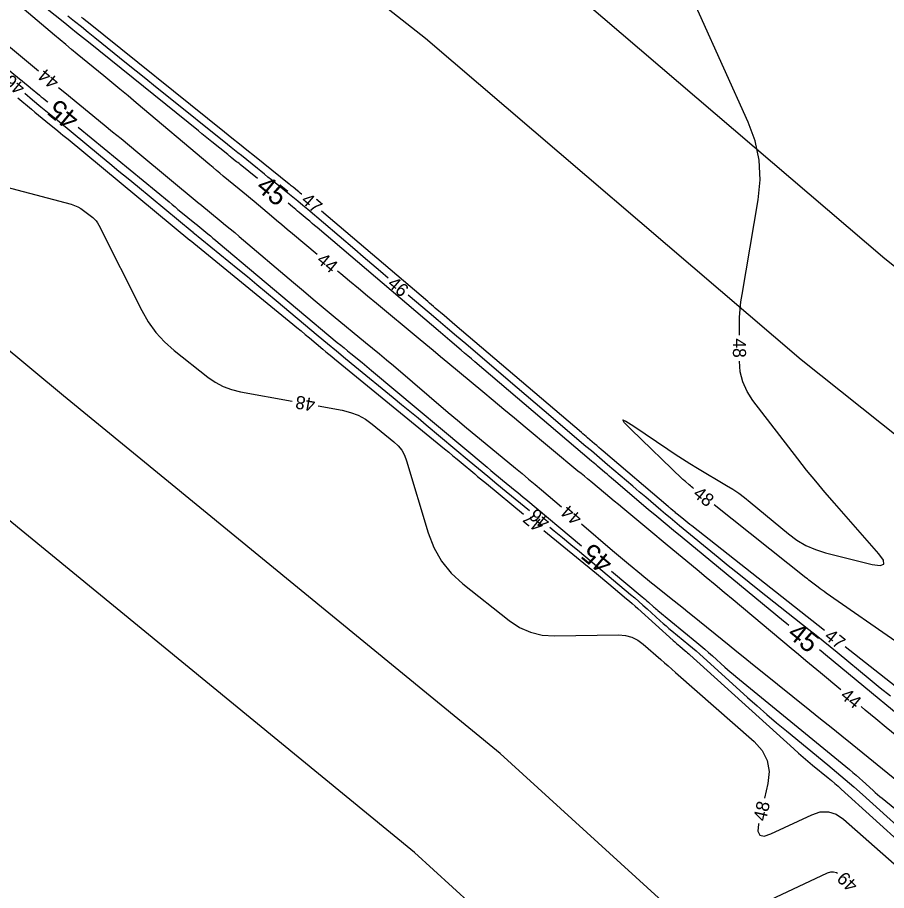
# Model space of a CAD drawing. Extents: x 2384780 to 2405861, y 547869 to 573706.
# Drawn here: x 2392904.4 to 2393037.1, y 552728.4 to 552861.7 of the extents above; entities that cross this region are included whole.
import ezdxf

# ---------------------------------------------------------------- set-up
doc = ezdxf.new("R2010")
doc.units = 0
for name, color, linetype in [('Old_Level_60', 7, 'Continuous'), ('Old_Level_61', 7, 'Continuous'), ('Prop Buffer Zone 1', 7, 'Continuous'), ('Prop Buffer Zone 2', 7, 'Continuous')]:
    doc.layers.add(name, color=color, linetype=linetype)

msp = doc.modelspace()

# ---------------------------------------------------------------- linework, layer by layer
at = {"layer": 'Old_Level_60'}
for points in [[(2393014.651, 552813.187), (2393014.651, 552814.72), (2393014.67575, 552815.89675), (2393014.75, 552817.06925), (2393014.874, 552818.23775), (2393015.0475, 552819.402), (2393017.507, 552833.8205), (2393017.8075, 552836.88125), (2393017.6545, 552839.88425), (2393017.048, 552842.82925), (2393015.9885, 552845.7165), (2393001.1235, 552878.74575)], [(2392950.20325, 552825.51225), (2392946.424, 552828.65525), (2392945.61225, 552829.33125), (2392944.8015, 552830.00825), (2392943.99175, 552830.68675), (2392943.183, 552831.36625), (2392940.5425, 552833.58775), (2392939.976, 552834.063), (2392939.40825, 552834.5365), (2392938.83875, 552835.0085), (2392938.26825, 552835.4785), (2392935.84425, 552837.46975), (2392935.32575, 552837.89725), (2392934.80825, 552838.32625), (2392934.29225, 552838.757), (2392933.7775, 552839.18925), (2392922.5335, 552848.666), (2392921.30425, 552849.69875), (2392920.0715, 552850.72775), (2392918.83575, 552851.753), (2392917.59675, 552852.77425), (2392913.54375, 552856.10375), (2392912.6765, 552856.819), (2392911.81225, 552857.53725), (2392910.9505, 552858.259), (2392910.0915, 552858.98375), (2392894.82625, 552871.91475)], [(2392961.027, 552821.88525), (2392959.836, 552822.899), (2392958.52525, 552824.015), (2392957.21475, 552825.13125), (2392955.90425, 552826.24775), (2392948.76075, 552832.33575), (2392948.0065, 552832.97425), (2392947.248, 552833.60775), (2392946.485, 552834.23625), (2392945.71825, 552834.8595), (2392943.20575, 552836.8875), (2392942.66725, 552837.32175), (2392942.1285, 552837.756), (2392941.58975, 552838.18975), (2392941.0505, 552838.62325), (2392938.60325, 552840.58975), (2392938.07875, 552841.011), (2392937.55425, 552841.4325), (2392937.03, 552841.85375), (2392936.5055, 552842.27525), (2392926.993, 552849.9185), (2392925.51425, 552851.10725), (2392924.036, 552852.297), (2392922.55825, 552853.48725), (2392921.08125, 552854.67825), (2392916.257, 552858.57025), (2392915.223, 552859.404), (2392914.1885, 552860.23725), (2392913.1535, 552861.06975), (2392912.11825, 552861.90175)], [(2392947.81175, 552834.6855), (2392947.785, 552834.7085), (2392947.58, 552834.8795), (2392947.374, 552835.04925), (2392947.167, 552835.2175), (2392946.4885, 552835.76525), (2392946.343, 552835.8825), (2392946.1975, 552835.99975), (2392946.052, 552836.117), (2392945.90625, 552836.234), (2392940.5875, 552840.50775), (2392939.44775, 552841.4235), (2392938.308, 552842.33925), (2392937.16825, 552843.25525), (2392936.0285, 552844.171), (2392915.011, 552861.05875), (2392915.0015, 552861.06625), (2392914.992, 552861.074), (2392914.98225, 552861.08175), (2392914.97275, 552861.0895), (2392914.9415, 552861.11475), (2392914.93475, 552861.12), (2392914.92825, 552861.1255), (2392914.9215, 552861.13075), (2392914.91475, 552861.13625), (2392914.51625, 552861.45625), (2392914.43175, 552861.52575), (2392914.349, 552861.59725), (2392914.26775, 552861.6705), (2392914.18825, 552861.7455)], [(2392900.331, 552859.599), (2392906.41775, 552854.54675), (2392907.621, 552853.54975)], [(2392905.52325, 552850.113), (2392906.743, 552849.10525), (2392908.00425, 552848.0635), (2392909.266, 552847.0225), (2392910.52825, 552845.98175), (2392917.10375, 552840.56225), (2392918.5125, 552839.4005), (2392919.921, 552838.2385), (2392921.329, 552837.076), (2392922.73675, 552835.91275), (2392931.11875, 552828.9845), (2392931.128, 552828.97675), (2392931.13725, 552828.96925), (2392931.14625, 552828.9615), (2392931.1555, 552828.954), (2392931.1855, 552828.92875), (2392931.19175, 552828.9235), (2392931.19825, 552828.918), (2392931.20475, 552828.91275), (2392931.21125, 552828.9075), (2392938.05975, 552823.3055), (2392939.5255, 552822.10275), (2392940.9875, 552820.89575), (2392942.446, 552819.68425), (2392943.90075, 552818.4685), (2392950.35075, 552813.061), (2392951.7345, 552811.90425), (2392953.122, 552810.75175), (2392954.51275, 552809.6035), (2392955.907, 552808.45925), (2392961.80175, 552803.63675), (2392963.06325, 552802.6015), (2392964.322, 552801.5625), (2392965.5775, 552800.52), (2392966.83, 552799.47375), (2392973.3925, 552793.97525), (2392974.8005, 552792.79925), (2392976.21175, 552791.62725), (2392977.6265, 552790.45925), (2392979.04475, 552789.2955), (2392982.592, 552786.393)], [(2392910.7075, 552851.0055), (2392911.64875, 552850.233), (2392917.66775, 552845.30125), (2392918.95675, 552844.2435), (2392920.24375, 552843.1835), (2392921.52925, 552842.1215), (2392922.813, 552841.05725), (2392932.17875, 552833.28025), (2392932.18825, 552833.27225), (2392932.1975, 552833.2645), (2392932.20675, 552833.25675), (2392932.216, 552833.24875), (2392932.2465, 552833.223), (2392932.253, 552833.2175), (2392932.2595, 552833.212), (2392932.266, 552833.20675), (2392932.2725, 552833.20125), (2392935.5135, 552830.54575), (2392936.20675, 552829.97525), (2392936.89725, 552829.4015), (2392937.58525, 552828.82475), (2392938.27075, 552828.24475), (2392946.5655, 552821.19325), (2392948.06875, 552819.9205), (2392949.57725, 552818.65425), (2392951.091, 552817.39425), (2392952.61, 552816.1405), (2392957.5805, 552812.05475), (2392958.64375, 552811.177), (2392959.703, 552810.2945), (2392960.75825, 552809.4075), (2392961.80975, 552808.51575), (2392970.18675, 552801.3795), (2392971.59025, 552800.18925), (2392972.999, 552799.0055), (2392974.41325, 552797.828), (2392975.8325, 552796.65675), (2392980.478, 552792.841), (2392981.47125, 552792.021), (2392982.46075, 552791.19625), (2392983.4465, 552790.36675), (2392984.428, 552789.5325), (2392987.47725, 552786.9285)], [(2392904.49125, 552849.3955), (2392906.543, 552847.6995), (2392907.09925, 552847.23975), (2392907.6555, 552846.7805), (2392908.21225, 552846.32125), (2392908.769, 552845.86225), (2392910.58775, 552844.363), (2392910.9775, 552844.0415), (2392911.367, 552843.72025), (2392911.7565, 552843.3985), (2392912.146, 552843.07675), (2392930.75675, 552827.69375), (2392930.76, 552827.69125), (2392930.763, 552827.68875), (2392930.76625, 552827.686), (2392930.7695, 552827.6835), (2392930.7795, 552827.67475), (2392930.78175, 552827.673), (2392930.784, 552827.67125), (2392930.78625, 552827.66925), (2392930.7885, 552827.6675), (2392946.4455, 552814.86025), (2392947.084, 552814.33625), (2392947.721, 552813.8105), (2392948.35625, 552813.28275), (2392948.99, 552812.753), (2392951.05775, 552811.0195), (2392951.5015, 552810.64875), (2392951.94625, 552810.27925), (2392952.392, 552809.911), (2392952.839, 552809.54425), (2392969.62475, 552795.81175), (2392970.263, 552795.288), (2392970.9, 552794.76225), (2392971.53525, 552794.23475), (2392972.169, 552793.70525), (2392974.2365, 552791.973), (2392974.68025, 552791.6025), (2392975.12475, 552791.23325), (2392975.5705, 552790.86525), (2392976.0175, 552790.4985), (2392981.702, 552785.84725)], [(2392884.42625, 552840.60725), (2392912.641, 552833.1545), (2392913.14875, 552832.99275), (2392913.63225, 552832.78225), (2392914.09125, 552832.523), (2392914.52625, 552832.215), (2392915.90675, 552831.129), (2392916.18675, 552830.88325), (2392916.43525, 552830.61175), (2392916.65175, 552830.31425), (2392916.83675, 552829.991), (2392923.4105, 552816.91125), (2392924.39525, 552815.1875), (2392925.548, 552813.60025), (2392926.8685, 552812.15), (2392928.357, 552810.83625), (2392933.49375, 552806.7685), (2392934.6295, 552805.97425), (2392935.8355, 552805.335), (2392937.1115, 552804.85075), (2392938.45775, 552804.5215), (2392946.3755, 552803.0785)], [(2393027.65, 552768.061), (2393007.35425, 552784.04225), (2393007.05725, 552784.2775), (2393006.7615, 552784.5145), (2393006.467, 552784.753), (2393006.174, 552784.993), (2393005.07525, 552785.89825), (2393004.94225, 552786.00825), (2393004.80975, 552786.1185), (2393004.67775, 552786.2295), (2393004.54625, 552786.341), (2393004.11725, 552786.70625), (2393004.02525, 552786.7845), (2393003.9335, 552786.86275), (2393003.8415, 552786.941), (2393003.7495, 552787.01925), (2392993.85825, 552795.44975), (2392993.52725, 552795.73175), (2392993.1965, 552796.0135), (2392992.8655, 552796.29525), (2392992.5345, 552796.577), (2392991.45325, 552797.49725), (2392991.2215, 552797.69425), (2392990.99, 552797.8915), (2392990.75825, 552798.089), (2392990.52675, 552798.28625), (2392971.21525, 552814.745), (2392970.80225, 552815.09675), (2392970.389, 552815.44875), (2392969.97575, 552815.8005), (2392969.5625, 552816.15225), (2392968.2125, 552817.30125), (2392967.923, 552817.5475), (2392967.63375, 552817.79375), (2392967.34475, 552818.04), (2392967.0555, 552818.28625), (2392950.85675, 552832.09175)], [(2393030.1475, 552758.9925), (2393027.01325, 552761.5885), (2393025.8915, 552762.519), (2393024.771, 552763.45125), (2393023.65175, 552764.38475), (2393022.534, 552765.32), (2393013.69075, 552772.72925), (2393012.316, 552773.8795), (2393010.9395, 552775.028), (2393009.5615, 552776.1745), (2393008.182, 552777.31925), (2393003.60925, 552781.10825), (2393002.675, 552781.88275), (2393001.741, 552782.65775), (2393000.80725, 552783.433), (2392999.874, 552784.20875), (2392996.82575, 552786.74325), (2392996.17275, 552787.2865), (2392995.5195, 552787.82975), (2392994.86625, 552788.37275), (2392994.213, 552788.916), (2392991.9425, 552790.80425), (2392991.45575, 552791.20875), (2392990.96925, 552791.6135), (2392990.48275, 552792.018), (2392989.996, 552792.42275), (2392981.932, 552799.128), (2392980.311, 552800.476), (2392978.68975, 552801.824), (2392977.0685, 552803.17225), (2392975.4475, 552804.52025), (2392970.15175, 552808.924), (2392969.017, 552809.86775), (2392967.88225, 552810.8115), (2392966.7475, 552811.755), (2392965.61275, 552812.69875), (2392959.23675, 552818.0005), (2392957.87025, 552819.1365), (2392956.504, 552820.2725), (2392955.13775, 552821.40875), (2392953.7715, 552822.545), (2392953.27875, 552822.95475)], [(2393037.6915, 552758.0235), (2393036.14375, 552759.27725), (2393034.6035, 552760.5405), (2393029.58425, 552764.68175), (2393028.506, 552765.56625), (2393027.423, 552766.44425), (2393026.335, 552767.31625), (2393025.242, 552768.182), (2393017.7095, 552774.11325), (2393016.11525, 552775.37575), (2393014.52775, 552776.64725), (2393012.9475, 552777.92725), (2393011.37425, 552779.216), (2393005.47775, 552784.07375), (2393004.7645, 552784.66375), (2393004.05375, 552785.2565), (2393003.34525, 552785.852), (2393002.63925, 552786.4505), (2393000.3365, 552788.41), (2392999.84325, 552788.83), (2392999.35, 552789.25), (2392998.85675, 552789.67), (2392998.3635, 552790.09025), (2392994.51175, 552793.37325), (2392993.68625, 552794.07675), (2392992.8605, 552794.78), (2392992.03475, 552795.48325), (2392991.209, 552796.186), (2392984.8285, 552801.61575), (2392983.4615, 552802.77925), (2392982.0945, 552803.94325), (2392980.72775, 552805.10725), (2392979.3615, 552806.27175), (2392972.84925, 552811.82175), (2392971.4535, 552813.011), (2392970.05775, 552814.2), (2392968.66175, 552815.38875), (2392967.26525, 552816.577), (2392964.07325, 552819.29325)], [(2393007.64975, 552789.75875), (2393007.53675, 552789.84925), (2393007.35175, 552789.99925), (2393007.1675, 552790.15075), (2393006.9845, 552790.30325), (2393006.38775, 552790.80325), (2393006.261, 552790.91125), (2393006.136, 552791.02175), (2393006.013, 552791.13425), (2393005.892, 552791.249), (2392998.10775, 552798.76175), (2392997.098, 552799.793), (2392996.8305, 552800.222), (2392997.30525, 552800.0485), (2392998.5225, 552799.2725), (2393003.71025, 552795.754), (2393004.8275, 552795.0085), (2393005.95525, 552794.27975), (2393007.09375, 552793.56825), (2393008.24325, 552792.8735), (2393012.69475, 552790.22825), (2393013.63575, 552789.64325), (2393014.55175, 552789.02275), (2393015.44225, 552788.36625), (2393016.30725, 552787.674), (2393022.13725, 552782.81675), (2393023.42775, 552781.85675), (2393024.80025, 552781.05875), (2393026.25475, 552780.4225), (2393027.79125, 552779.948), (2393034.928, 552778.16775), (2393036.13625, 552777.98225), (2393036.70275, 552778.1885), (2393036.627, 552778.78625), (2393035.9095, 552779.776), (2393029.14025, 552787.5035), (2393027.703, 552789.17025), (2393026.2925, 552790.859), (2393024.90875, 552792.56975), (2393023.5515, 552794.30225), (2393016.70725, 552803.18225), (2393015.8075, 552804.56), (2393015.165, 552806.02525), (2393014.7795, 552807.578), (2393014.6535, 552809.18725)], [(2392950.31075, 552802.36125), (2392953.9915, 552801.69025), (2392955.242, 552801.3825), (2392956.4245, 552800.92775), (2392957.5395, 552800.32575), (2392958.5865, 552799.5765), (2392961.89675, 552796.8885), (2392962.55025, 552796.275), (2392963.0915, 552795.58675), (2392963.52075, 552794.8235), (2392963.838, 552793.98525), (2392967.12425, 552782.97175), (2392967.982, 552780.716), (2392969.1465, 552778.668), (2392970.618, 552776.82825), (2392972.3965, 552775.19675), (2392979.482, 552769.59425), (2392981.0525, 552768.547), (2392982.72725, 552767.8065), (2392984.50625, 552767.37275), (2392986.3895, 552767.24575), (2392996.179, 552767.379), (2392997.227, 552767.30275), (2392998.208, 552767.04425), (2392999.12175, 552766.6035), (2392999.96825, 552765.98075), (2393002.62375, 552763.649), (2393003.193, 552763.14925), (2393003.762, 552762.6495), (2393004.331, 552762.14975), (2393004.9, 552761.65025), (2393016.90225, 552751.11075), (2393018.1325, 552749.7455), (2393018.889, 552748.22575), (2393019.1715, 552746.55225), (2393018.98, 552744.72425), (2393018.473, 552742.46925)], [(2393039.0435, 552766.036), (2393027.8805, 552773.779), (2393027.56725, 552773.999), (2393027.2565, 552774.2225), (2393026.94825, 552774.4495), (2393026.64275, 552774.68025), (2393025.649, 552775.4395), (2393025.4365, 552775.60275), (2393025.22475, 552775.767), (2393025.01375, 552775.93225), (2393024.80375, 552776.09875), (2393010.7785, 552787.26675)], [(2392984.79775, 552783.31425), (2392992.804, 552776.76325), (2392993.44225, 552776.23975), (2392994.07875, 552775.71425), (2392994.714, 552775.187), (2392995.34775, 552774.65775), (2392997.41525, 552772.9265), (2392997.85625, 552772.5535), (2392998.29375, 552772.17575), (2392998.72725, 552771.794), (2392999.157, 552771.40775), (2393004.50925, 552766.5475), (2393004.75925, 552766.32325), (2393005.012, 552766.10225), (2393005.26775, 552765.8845), (2393005.526, 552765.66975), (2393006.374, 552764.9735), (2393006.55475, 552764.82325), (2393006.73375, 552764.67075), (2393006.91075, 552764.516), (2393007.08575, 552764.359), (2393022.94325, 552749.97475), (2393023.64675, 552749.3445), (2393024.35825, 552748.7235), (2393025.07725, 552748.11175), (2393025.80425, 552747.50875), (2393028.192, 552745.55425), (2393028.701, 552745.1325), (2393029.2045, 552744.70425), (2393029.703, 552744.27), (2393030.19575, 552743.8295), (2393044.6965, 552730.7095)], [(2392985.687, 552783.859), (2392986.35925, 552783.30725), (2392987.646, 552782.2455), (2392988.9295, 552781.18), (2392990.21, 552780.11075), (2392998.018, 552773.5725), (2392998.65625, 552773.0325), (2392999.289, 552772.48625), (2392999.91625, 552771.93375), (2393000.538, 552771.375), (2393002.55975, 552769.539), (2393002.9955, 552769.14825), (2393003.436, 552768.76325), (2393003.881, 552768.3835), (2393004.331, 552768.0095), (2393006.93525, 552765.8715), (2393007.4905, 552765.41), (2393008.03975, 552764.94175), (2393008.58325, 552764.46675), (2393009.121, 552763.985), (2393015.88975, 552757.84525), (2393017.34825, 552756.53875), (2393018.823, 552755.25125), (2393020.314, 552753.98275), (2393021.82125, 552752.733), (2393028.134, 552747.5655), (2393029.47975, 552746.44975), (2393030.81125, 552745.318), (2393032.12875, 552744.16975), (2393033.43225, 552743.005), (2393038.72975, 552738.21175)], [(2392990.519, 552784.331), (2392995.26275, 552780.28), (2392995.86675, 552779.767), (2392996.473, 552779.25675), (2392997.08175, 552778.7495), (2392997.69325, 552778.24525), (2392999.69425, 552776.60275), (2393000.1235, 552776.2515), (2393000.55375, 552775.9015), (2393000.98525, 552775.553), (2393001.41775, 552775.2055), (2393004.69, 552772.5855), (2393005.39075, 552772.0235), (2393006.09075, 552771.4605), (2393006.78975, 552770.89625), (2393007.488, 552770.33125), (2393013.06675, 552765.809), (2393014.26275, 552764.84075), (2393015.46025, 552763.874), (2393016.659, 552762.90925), (2393017.859, 552761.946), (2393025.41, 552755.89375), (2393027.027, 552754.59575), (2393028.64225, 552753.2955), (2393030.25575, 552751.99275), (2393031.86725, 552750.68775), (2393038.93575, 552744.95575)], [(2393049.17, 552751.1145), (2393030.77525, 552765.56475)], [(2393038.65125, 552751.92075), (2393037.05375, 552753.256), (2393035.45475, 552754.5895), (2393033.85375, 552755.92075), (2393033.2275, 552756.44025)], [(2393017.59575, 552738.56675), (2393017.581, 552738.50125), (2393017.47325, 552737.40725), (2393017.74975, 552736.79175), (2393018.41025, 552736.65525), (2393019.45525, 552736.99725), (2393025.67525, 552739.92125), (2393026.97975, 552740.348), (2393028.2275, 552740.375), (2393029.41875, 552740.002), (2393030.553, 552739.22925), (2393045.147, 552726.39625)], [(2393029.605, 552730.94125), (2393029.454, 552731.044), (2393029.01125, 552731.18275), (2393028.54725, 552731.17275), (2393028.06225, 552731.014), (2393014.092, 552724.44675), (2393013.42275, 552724.05075), (2393013.22525, 552723.71425), (2393013.5, 552723.43725), (2393014.2465, 552723.21975)]]:
    msp.add_lwpolyline(points, dxfattribs=at)
at = {"layer": 'Old_Level_61'}
for points in [[(2392885.6125, 552868.0935), (2392904.7385, 552852.33025), (2392905.15575, 552851.98625), (2392905.573, 552851.642), (2392905.99, 552851.29775), (2392906.40675, 552850.95325), (2392907.76825, 552849.82775), (2392908.06025, 552849.5865), (2392908.352, 552849.3455), (2392908.644, 552849.10475), (2392908.93625, 552848.86375), (2392909.043, 552848.77575)], [(2392941.0645, 552837.0885), (2392938.43775, 552839.20875), (2392938.249, 552839.36075), (2392938.06025, 552839.513), (2392937.8715, 552839.665), (2392937.6825, 552839.81675), (2392937.06525, 552840.31275), (2392936.933, 552840.41925), (2392936.80075, 552840.5255), (2392936.6685, 552840.63175), (2392936.53625, 552840.738), (2392934.11525, 552842.68325), (2392933.5965, 552843.10025), (2392933.078, 552843.5175), (2392932.55975, 552843.935), (2392932.04175, 552844.35275), (2392915.24475, 552857.90375), (2392914.3475, 552858.62725), (2392913.44975, 552859.35), (2392912.55175, 552860.0725), (2392911.6535, 552860.7945), (2392908.718, 552863.152)], [(2392913.673, 552844.9595), (2392927.56475, 552833.50975), (2392928.0205, 552833.134), (2392928.476, 552832.75825), (2392928.9315, 552832.382), (2392929.38675, 552832.006), (2392931.48075, 552830.27525), (2392931.496, 552830.2625), (2392931.51125, 552830.24975), (2392931.5265, 552830.23725), (2392931.5415, 552830.2245), (2392931.59125, 552830.18275), (2392931.60175, 552830.174), (2392931.6125, 552830.165), (2392931.62325, 552830.15625), (2392931.634, 552830.1475), (2392933.476, 552828.6405), (2392933.87025, 552828.317), (2392934.2635, 552827.9925), (2392934.65575, 552827.6665), (2392935.047, 552827.3395), (2392953.25625, 552812.07375), (2392953.77175, 552811.64275), (2392954.28875, 552811.2135), (2392954.80675, 552810.78575), (2392955.32625, 552810.3595), (2392957.025, 552808.9695), (2392957.3885, 552808.67125), (2392957.75125, 552808.37175), (2392958.11325, 552808.07125), (2392958.47425, 552807.76975), (2392976.118, 552792.98675), (2392976.70325, 552792.498), (2392977.29, 552792.01075), (2392977.87825, 552791.52525), (2392978.46775, 552791.0415), (2392980.39575, 552789.46375), (2392980.8085, 552789.12525), (2392981.22, 552788.78525), (2392981.63075, 552788.4445), (2392982.04075, 552788.10225), (2392990.5345, 552780.98975)], [(2393022.16525, 552768.84), (2393021.8315, 552769.1105), (2393021.39225, 552769.47025), (2393005.88, 552782.2495), (2393004.58675, 552783.31925), (2393003.2975, 552784.3945), (2393002.0125, 552785.47475), (2393000.732, 552786.56), (2392995.439, 552791.0645), (2392995.10275, 552791.35075), (2392994.76625, 552791.637), (2392994.43, 552791.9235), (2392994.094, 552792.21), (2392992.99575, 552793.146), (2392992.7605, 552793.3465), (2392992.525, 552793.547), (2392992.28975, 552793.7475), (2392992.05425, 552793.94775), (2392974.2405, 552809.107), (2392973.7195, 552809.5505), (2392973.1985, 552809.994), (2392972.67775, 552810.4375), (2392972.157, 552810.88125), (2392970.456, 552812.331), (2392970.0915, 552812.6415), (2392969.727, 552812.952), (2392969.3625, 552813.2625), (2392968.99775, 552813.57275), (2392950.162, 552829.6005), (2392949.789, 552829.918), (2392949.416, 552830.2355), (2392949.043, 552830.55325), (2392948.67025, 552830.871), (2392947.45225, 552831.909), (2392947.1905, 552832.1305), (2392946.92725, 552832.35025), (2392946.66275, 552832.56825), (2392946.3965, 552832.7845), (2392945.7335, 552833.31975)], [(2392995.1345, 552777.13775), (2392999.818, 552773.216), (2393000.05725, 552773.0135), (2393000.29475, 552772.80875), (2393000.52975, 552772.6015), (2393000.763, 552772.39175), (2393001.52125, 552771.70325), (2393001.6845, 552771.55675), (2393001.84975, 552771.4125), (2393002.01675, 552771.27), (2393002.1855, 552771.12975), (2393008.15275, 552766.231), (2393008.756, 552765.7295), (2393009.35275, 552765.22075), (2393009.94325, 552764.70475), (2393010.5275, 552764.1815), (2393012.42525, 552762.45975), (2393012.83425, 552762.0935), (2393013.24775, 552761.7325), (2393013.66575, 552761.37675), (2393014.0885, 552761.0265), (2393031.44075, 552746.822), (2393031.94975, 552746.40025), (2393032.45325, 552745.97225), (2393032.95125, 552745.53825), (2393033.44425, 552745.09775), (2393035.04525, 552743.649), (2393035.39025, 552743.34075), (2393035.73925, 552743.037), (2393036.092, 552742.73775), (2393036.4485, 552742.443), (2393052.71, 552729.17)], [(2393045.03975, 552750.11975), (2393027.76825, 552764.3705), (2393027.14125, 552764.885), (2393026.8645, 552765.1095)]]:
    msp.add_lwpolyline(points, dxfattribs=at)
at = {"layer": 'Prop Buffer Zone 1'}
for points in [[(2392814.318, 552987.25575), (2392856.858, 552947.124), (2392910.191, 552903.03325), (2392966.7405, 552858.544), (2393024.089, 552809.45125), (2393072.89275, 552770.57925), (2393091.28025, 552755.58975), (2393111.64975, 552748.752), (2393123.2175, 552748.8085)], [(2393077.23476, 552672.56616), (2393032.202, 552699.94225), (2392978.104, 552749.3055), (2392911.4755, 552803.88425), (2392846.701, 552857.72175), (2392779.18875, 552913.433)]]:
    msp.add_lwpolyline(points, dxfattribs=at)
at = {"layer": 'Prop Buffer Zone 2'}
for points in [[(2392828.79425, 553001.09425), (2392870.106, 552962.12125), (2392922.74775, 552918.602), (2392979.43225, 552874.0065), (2393036.82625, 552824.87475), (2393085.442, 552786.15275), (2393101.09575, 552773.3915), (2393114.8695, 552768.768), (2393121.7695, 552768.79875)], [(2393036.48837, 552673.93088), (2393020.1545, 552683.8605), (2392965.0175, 552734.172), (2392898.7465, 552788.45775), (2392833.94425, 552842.31825), (2392766.45925, 552898.007)]]:
    msp.add_lwpolyline(points, dxfattribs=at)

# ---------------------------------------------------------------- texts
at = {"layer": 'Old_Level_60'}
for s, rotation, p in [('44', 140.5002611, (2392910.94125, 552852.10625)), ('46', 140.4224778, (2392905.75975, 552851.21475)), ('47', 319.5719611, (2392947.59525, 552833.557)), ('44', 320.2533389, (2392949.9635, 552824.411)), ('46', 319.6046694, (2392960.77475, 552820.787)), ('48', 270.0350639, (2393013.65, 552812.69025)), ('48', 169.6705389, (2392950.00175, 552803.434)), ('48', 321.4660028, (2393007.41475, 552788.66725)), ('44', 139.5041556, (2392990.77325, 552785.429)), ('47', 140.7093667, (2392984.99225, 552784.44725)), ('46', 140.6931139, (2392985.91875, 552784.9625)), ('47', 321.385025, (2393027.462, 552766.9175)), ('44', 320.3532667, (2393029.91, 552757.891)), ('48', 77.3289278, (2393018.68025, 552738.8315)), ('49', 135.6707417, (2393032.88925, 552729.33325))]:
    msp.add_text(s, height=2, rotation=rotation, dxfattribs=at).set_placement(p)
at = {"layer": 'Old_Level_61'}
for rotation, p in [(140.5039806, (2392914.08925, 552846.5605)), (321.0906028, (2392940.66475, 552835.4835)), (140.05805, (2392995.56325, 552778.73525)), (321.5538722, (2393021.78075, 552767.23475))]:
    msp.add_text('45', height=3, rotation=rotation, dxfattribs=at).set_placement(p)

doc.saveas('drawing.dxf')
